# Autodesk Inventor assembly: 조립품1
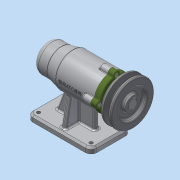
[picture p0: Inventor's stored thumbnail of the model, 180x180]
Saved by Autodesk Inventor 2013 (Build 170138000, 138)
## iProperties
Created: 2019-07
Part Number: 조립품1
Document SubType Name: Assembly
Designer: dg
Author: dg
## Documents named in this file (12)
- C:\Users\dg\Desktop\490704V1044\조립품1.iam
- C:\Users\dg\Desktop\490704V1044\V벨트풀리.ipt
- C:\Users\dg\Desktop\490704V1044\멈춤나사 M3.ipt
- C:\Users\dg\Desktop\490704V1044\베어링 6004.ipt
- C:\Users\dg\Desktop\490704V1044\베어링 51202.ipt
- C:\Users\dg\Desktop\490704V1044\본체.ipt
- C:\Users\dg\Desktop\490704V1044\볼트 M4.ipt
- C:\Users\dg\Desktop\490704V1044\어댑터슬리브.ipt
- C:\Users\dg\Desktop\490704V1044\오일 실.ipt
- C:\Users\dg\Desktop\490704V1044\축.ipt
- C:\Users\dg\Desktop\490704V1044\커버.ipt
- C:\Users\dg\Desktop\490704V1044\키 5 x 5 x 16.ipt
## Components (1 placed, 1 different names)
1. V벨트풀리:1
